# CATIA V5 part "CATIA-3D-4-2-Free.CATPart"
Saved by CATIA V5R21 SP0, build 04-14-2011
Part number: CATIA-3D-4-2-Free
Bounding box of the stored display mesh (mm): x -100 to 0, y -25 to 63.997, z -44 to 56
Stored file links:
  C:\Users\Rasoul Mohammadi\Desktop\CATIA-Free\3D\CATIA-3D-4-2-Free.CATPart
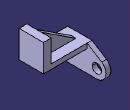
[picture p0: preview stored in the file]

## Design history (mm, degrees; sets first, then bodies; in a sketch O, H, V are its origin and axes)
Body1 (main body)
  Sketch1 on zx-plane, origin (0, 0, 0), H (-1, 0, 0), V (0, 0, 1)
    point P1 (0, 56)
    line L1 (0, 56) -> (0, 0)
    line L2 (0, 0) -> (90, 0)
    line L3 (90, 0) -> (90, 10)
    line L4 (90, 10) -> (16, 10)
    line L5 (16, 10) -> (16, 56)
    line L6 (16, 56) -> (0, 56)
    length L6 = 16
    length L1 = 56
    length L3 = 10
    length L2 = 90
    coincidence: P1 V
    vertical: L1 V, L3 V, L5 V
    horizontal: L2 H, L4 H, L6 H
  Pad1: profile Sketch1, direction (0, 1, 0), length 25, mirrored extent
  Sketch2 on face of Pad1 from Sketch1.L3, origin (-90, 0, 0), H (0, -1, 0), V (0, 0, 1)
    projected line E1 (25, 10) -> (-25, 10) from edge [face of Pad1 from Sketch1.L4 | face of Pad1 from Sketch1.L3]
    line L1 (25, 10) -> (25, -44)
    line L2 (25, -44) -> (-45, -44)
    arc A1 centre (-45, -25) radius 19 from (-55.1062, -8.9107) to (-45, -44) ccw
    point P5 (-45, -25)
    line L3 (-25, 10) -> (-55.1062, -8.9107)
    circle A2 centre (-45, -25) radius 9.5
    distance P5 L1 = 70
    radius A1 = 19
    length L1 = 54
    radius A2 = 9.5
    vertical: L1 V
    horizontal: L2 H
    tangency: A1 L2, L3 A1
  Pad2: profile Sketch2, direction (-1, 0, 0), length 10
  Sketch3 on zx-plane, origin (0, 0, 0), H (-1, 0, 0), V (0, 0, 1)
    line L1 (16, 56) -> (87, 10)
    point P1 (16, 56)
    point P2 (87, 10)
    reference projected line E1 (90, 10) -> (16, 10) from edge [face of Pad2 | end face of Pad1]
    reference projected point E2 (16, 56) from vertex [face of Pad1 from Sketch1.L6 | end face of Pad1 | face of Pad1 from Sketch1.L5]
    reference projected line E3 (100, 10) -> (100, -8.9107) from edge [face of Pad2 from Sketch2.L3 | end face of Pad2]
    distance P2 E3 = 13
    coincidence: P2 E1, P1 E2
  Stiffener1: ExtendedProfile Sketch3, ThicknessTop 0, ThicknessValue 10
